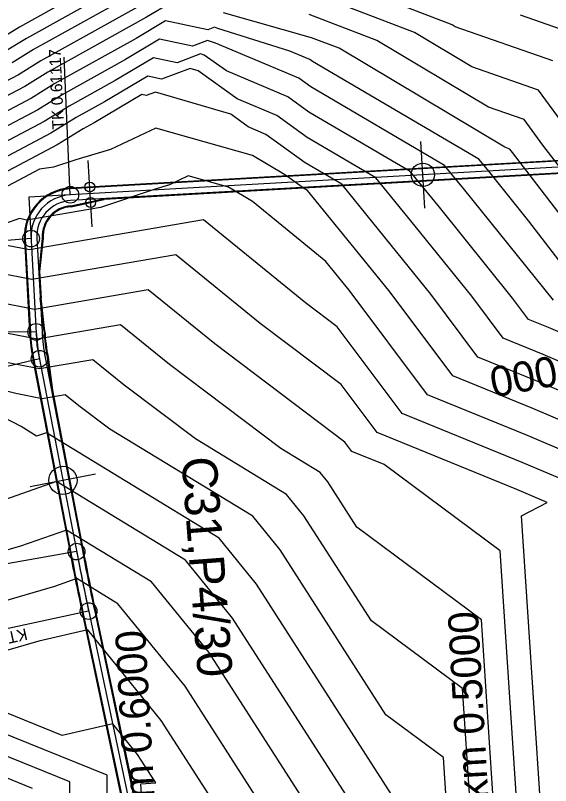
# Model space of a CAD drawing. Extents: x -549394 to -546608, y -1037055 to -1033629.
# Drawn here: x -547213.9 to -547053.3, y -1036262.8 to -1036031.6 of the extents above; entities that cross this region are included whole.
import ezdxf

# ---------------------------------------------------------------- set-up
doc = ezdxf.new("R2010")
doc.units = 0
for name, color, linetype in [('hlavni_vrst', 7, 'Continuous'), ('norm_vrst', 7, 'Continuous'), ('POLYGONY_SITUACE_PO', 7, 'Continuous'), ('u_sirka_7m', 7, 'Continuous'), ('x_navrh_C31', 7, 'Continuous'), ('x_osa_C31', 7, 'Continuous'), ('x_popis_oblouky_C31', 7, 'Continuous'), ('x_popis_pricne_rezy_C31', 7, 'Continuous'), ('x_popis_vely_C31', 7, 'Continuous')]:
    doc.layers.add(name, color=color, linetype=linetype)

msp = doc.modelspace()

# ---------------------------------------------------------------- linework, layer by layer
at = {"layer": 'hlavni_vrst'}
for p, q in [((-547161.94, -1036006.74), (-547212.7, -1036035.07)), ((-547048.3, -1036036.36), (-547062.3, -1036031.47)), ((-547168.82, -1036033.21), (-547177.7, -1036038.46)), ((-547156.15, -1036035.89), (-547168.82, -1036033.21)), ((-547212.7, -1036035.07), (-547218.78, -1036038.81)), ((-547154.16, -1036035.14), (-547156.15, -1036035.89)), ((-547153.11, -1036035.46), (-547154.16, -1036035.14)), ((-547131.51, -1036042.32), (-547153.11, -1036035.46)), ((-547177.7, -1036038.46), (-547202.05, -1036052.05)), ((-547125.59, -1036044.82), (-547131.51, -1036042.32)), ((-547124.74, -1036045.44), (-547125.59, -1036044.82)), ((-547074.84, -1036074.7), (-547124.74, -1036045.44)), ((-547202.05, -1036052.05), (-547209.1, -1036056.41)), ((-547209.1, -1036056.41), (-547236.25, -1036070.69)), ((-547171.78, -1036065.48), (-547185.32, -1036071.84)), ((-547142.72, -1036073.65), (-547171.78, -1036065.48)), ((-547185.32, -1036071.84), (-547195.72, -1036074.9)), ((-547132.86, -1036079.54), (-547142.72, -1036073.65)), ((-547195.72, -1036074.9), (-547202.48, -1036077.18)), ((-547072.26, -1036077.87), (-547074.84, -1036074.7)), ((-547206.64, -1036077.79), (-547230.36, -1036090.28)), ((-547202.48, -1036077.18), (-547206.64, -1036077.79)), ((-547059.82, -1036093.31), (-547072.26, -1036077.87)), ((-547127.44, -1036083.49), (-547132.86, -1036079.54)), ((-547126.27, -1036084.17), (-547127.44, -1036083.49)), ((-547108.3, -1036106.18), (-547126.27, -1036084.17)), ((-547046.99, -1036110.07), (-547059.82, -1036093.31)), ((-547101.47, -1036114.66), (-547108.3, -1036106.18)), ((-547082.66, -1036139.83), (-547101.47, -1036114.66)), ((-547207.41, -1036128.8), (-547228.09, -1036124.77)), ((-547182.34, -1036124.49), (-547207.41, -1036128.8)), ((-547167.65, -1036136.42), (-547182.34, -1036124.49)), ((-547134.25, -1036161.63), (-547167.65, -1036136.42)), ((-547058.66, -1036149.61), (-547082.66, -1036139.83)), ((-547033.64, -1036160.27), (-547058.66, -1036149.61)), ((-547122.45, -1036168.83), (-547134.25, -1036161.63)), ((-547120.18, -1036171.62), (-547122.45, -1036168.83)), ((-547111.44, -1036185.24), (-547120.18, -1036171.62)), ((-547198.53, -1036186.1), (-547212.4, -1036190.97)), ((-547173.02, -1036201.66), (-547198.53, -1036186.1)), ((-547074.04, -1036213.03), (-547111.44, -1036185.24)), ((-547212.4, -1036190.97), (-547223.21, -1036194.11)), ((-547155.85, -1036222.78), (-547173.02, -1036201.66)), ((-547069.17, -1036287.31), (-547074.04, -1036213.03)), ((-547118.07, -1036281.61), (-547155.85, -1036222.78)), ((-547197.57, -1036261.66), (-547233.92, -1036247.04)), ((-547197.5, -1036286.3), (-547197.57, -1036261.66))]:
    msp.add_line(p, q, dxfattribs=at)
at = {"layer": 'norm_vrst'}
for p, q in [((-547165.09, -1036013.08), (-547210.57, -1036038.46)), ((-547082.87, -1036034.38), (-547127.13, -1036017.3)), ((-547168.24, -1036019.43), (-547208.44, -1036041.86)), ((-547094.17, -1036036.74), (-547126.44, -1036024.29)), ((-547171.39, -1036025.77), (-547206.31, -1036045.26)), ((-547167.03, -1036027.67), (-547174.54, -1036032.12)), ((-547174.54, -1036032.12), (-547204.18, -1036048.65)), ((-547125.05, -1036038.26), (-547151.43, -1036030.85)), ((-547105.47, -1036039.1), (-547125.74, -1036031.27)), ((-547081.89, -1036034.96), (-547082.87, -1036034.38)), ((-547076.93, -1036047.04), (-547094.17, -1036036.74)), ((-547052.6, -1036045.2), (-547081.89, -1036034.96)), ((-547210.57, -1036038.46), (-547216.84, -1036042.33)), ((-547170.62, -1036038.75), (-547180.85, -1036044.81)), ((-547160.77, -1036040.83), (-547170.62, -1036038.75)), ((-547156.25, -1036039.14), (-547160.77, -1036040.83)), ((-547153.89, -1036039.87), (-547156.25, -1036039.14)), ((-547116.77, -1036041.45), (-547125.05, -1036038.26)), ((-547071.96, -1036059.11), (-547105.47, -1036039.1)), ((-547153.89, -1036039.87), (-547153.89, -1036039.87)), ((-547128.86, -1036050.44), (-547153.89, -1036039.87)), ((-547153.89, -1036039.87), (-547153.89, -1036039.87)), ((-547066.99, -1036071.18), (-547116.77, -1036041.45)), ((-547208.44, -1036041.86), (-547214.91, -1036045.85)), ((-547158.35, -1036043.14), (-547165.4, -1036045.77)), ((-547157.24, -1036043.48), (-547158.35, -1036043.14)), ((-547150.6, -1036048.26), (-547157.24, -1036043.48)), ((-547206.31, -1036045.26), (-547212.97, -1036049.37)), ((-547180.85, -1036044.81), (-547199.92, -1036055.45)), ((-547172.41, -1036044.29), (-547184, -1036051.15)), ((-547165.4, -1036045.77), (-547172.41, -1036044.29)), ((-547161.44, -1036047.51), (-547170.02, -1036050.71)), ((-547159.02, -1036048.23), (-547161.44, -1036047.51)), ((-547147.31, -1036056.65), (-547159.02, -1036048.23)), ((-547132.14, -1036056.06), (-547150.6, -1036048.26)), ((-547056.91, -1036054.03), (-547076.93, -1036047.04)), ((-547212.97, -1036049.37), (-547238.6, -1036062.86)), ((-547204.18, -1036048.65), (-547211.04, -1036052.89)), ((-547174.2, -1036049.83), (-547187.15, -1036057.5)), ((-547170.02, -1036050.71), (-547174.2, -1036049.83)), ((-547125.28, -1036053.05), (-547128.86, -1036050.44)), ((-547211.04, -1036052.89), (-547237.42, -1036066.77)), ((-547184, -1036051.15), (-547197.78, -1036058.84)), ((-547085.12, -1036076.6), (-547125.28, -1036053.05)), ((-547199.92, -1036055.45), (-547207.17, -1036059.92)), ((-547176, -1036055.37), (-547190.3, -1036063.84)), ((-547174.64, -1036055.66), (-547176, -1036055.37)), ((-547171.86, -1036054.62), (-547174.64, -1036055.66)), ((-547149.26, -1036061.27), (-547171.86, -1036054.62)), ((-547046.49, -1036068.33), (-547056.91, -1036054.03)), ((-547187.15, -1036057.5), (-547195.65, -1036062.24)), ((-547135.42, -1036061.67), (-547147.31, -1036056.65)), ((-547125.82, -1036060.66), (-547132.14, -1036056.06)), ((-547207.17, -1036059.92), (-547235.07, -1036074.61)), ((-547197.78, -1036058.84), (-547205.23, -1036063.44)), ((-547061.21, -1036062.86), (-547071.96, -1036059.11)), ((-547195.65, -1036062.24), (-547203.3, -1036066.96)), ((-547144.02, -1036065.04), (-547149.26, -1036061.27)), ((-547126.36, -1036068.27), (-547135.42, -1036061.67)), ((-547095.41, -1036078.49), (-547125.82, -1036060.66)), ((-547205.23, -1036063.44), (-547233.89, -1036078.53)), ((-547190.3, -1036063.84), (-547193.52, -1036065.64)), ((-547055.61, -1036070.55), (-547061.21, -1036062.86)), ((-547203.3, -1036066.96), (-547232.71, -1036082.44)), ((-547193.52, -1036065.64), (-547201.37, -1036070.48)), ((-547138.7, -1036067.29), (-547144.02, -1036065.04)), ((-547126.9, -1036075.88), (-547138.7, -1036067.29)), ((-547105.7, -1036080.38), (-547126.36, -1036068.27)), ((-547201.37, -1036070.48), (-547231.54, -1036086.36)), ((-547065.51, -1036071.7), (-547066.99, -1036071.18)), ((-547036.25, -1036095.83), (-547055.61, -1036070.55)), ((-547064.74, -1036072.76), (-547065.51, -1036071.7)), ((-547041.62, -1036102.95), (-547064.74, -1036072.76)), ((-547115.98, -1036082.28), (-547126.9, -1036075.88)), ((-547086.67, -1036089.19), (-547095.41, -1036078.49)), ((-547079.46, -1036083.53), (-547085.12, -1036076.6)), ((-547162.01, -1036079.79), (-547167.64, -1036082.44)), ((-547149.95, -1036083.19), (-547162.01, -1036079.79)), ((-547093.88, -1036094.86), (-547105.7, -1036080.38)), ((-547167.64, -1036082.44), (-547171.95, -1036083.71)), ((-547142.76, -1036087.48), (-547149.95, -1036083.19)), ((-547101.09, -1036100.52), (-547115.98, -1036082.28)), ((-547171.95, -1036083.71), (-547188.34, -1036089.23)), ((-547052.42, -1036117.11), (-547079.46, -1036083.53)), ((-547120.72, -1036105.46), (-547142.76, -1036087.48)), ((-547188.34, -1036089.23), (-547210.45, -1036093.02)), ((-547064.69, -1036116.5), (-547086.67, -1036089.19)), ((-547212.67, -1036092.59), (-547217.14, -1036094.19)), ((-547210.45, -1036093.02), (-547212.67, -1036092.59)), ((-547157.48, -1036093), (-547209.69, -1036101.97)), ((-547126.87, -1036117.85), (-547157.48, -1036093)), ((-547076.95, -1036115.89), (-547093.88, -1036094.86)), ((-547209.69, -1036101.97), (-547216.52, -1036100.64)), ((-547089.21, -1036115.27), (-547101.09, -1036100.52)), ((-547165.77, -1036103.5), (-547208.93, -1036110.91)), ((-547140.46, -1036124.04), (-547165.77, -1036103.5)), ((-547115.51, -1036111.85), (-547120.72, -1036105.46)), ((-547208.93, -1036110.91), (-547220.38, -1036108.68)), ((-547113.74, -1036114.04), (-547115.51, -1036111.85)), ((-547174.06, -1036114), (-547208.17, -1036119.85)), ((-547154.05, -1036130.23), (-547174.06, -1036114)), ((-547090.23, -1036145.49), (-547113.74, -1036114.04)), ((-547075.09, -1036134.17), (-547089.21, -1036115.27)), ((-547208.17, -1036119.85), (-547224.23, -1036116.72)), ((-547117.29, -1036125.08), (-547126.87, -1036117.85)), ((-547067.52, -1036128.5), (-547076.95, -1036115.89)), ((-547059.95, -1036122.84), (-547064.69, -1036116.5)), ((-547116.16, -1036142.38), (-547140.46, -1036124.04)), ((-547053.9, -1036125.3), (-547059.95, -1036122.84)), ((-547097.8, -1036151.15), (-547117.29, -1036125.08)), ((-547047.6, -1036127.99), (-547053.9, -1036125.3)), ((-547055.49, -1036133.41), (-547067.52, -1036128.5)), ((-547115.03, -1036159.69), (-547154.05, -1036130.23)), ((-547042.95, -1036138.75), (-547055.49, -1036133.41)), ((-547206.65, -1036137.74), (-547224.8, -1036134.2)), ((-547190.63, -1036134.99), (-547206.65, -1036137.74)), ((-547181.24, -1036142.61), (-547190.63, -1036134.99)), ((-547057.08, -1036141.51), (-547075.09, -1036134.17)), ((-547213.78, -1036145.14), (-547230.31, -1036140.87)), ((-547159.9, -1036158.72), (-547181.24, -1036142.61)), ((-547105.37, -1036156.82), (-547116.16, -1036142.38)), ((-547038.29, -1036149.51), (-547057.08, -1036141.51)), ((-547205.89, -1036146.68), (-547213.78, -1036145.14)), ((-547198.92, -1036145.49), (-547205.89, -1036146.68)), ((-547194.83, -1036148.8), (-547198.92, -1036145.49)), ((-547060.25, -1036157.72), (-547090.23, -1036145.49)), ((-547185.55, -1036155.81), (-547194.83, -1036148.8)), ((-547212.13, -1036155.02), (-547217.37, -1036152.31)), ((-547061.84, -1036165.82), (-547097.8, -1036151.15)), ((-547207.53, -1036157.95), (-547212.13, -1036155.02)), ((-547204.6, -1036156.93), (-547207.53, -1036157.95)), ((-547152.79, -1036188.53), (-547204.6, -1036156.93)), ((-547142.68, -1036181.96), (-547185.55, -1036155.81)), ((-547063.42, -1036173.92), (-547105.37, -1036156.82)), ((-547132.56, -1036175.4), (-547159.9, -1036158.72)), ((-547028.99, -1036171.02), (-547060.25, -1036157.72)), ((-547112.94, -1036162.48), (-547115.03, -1036159.69)), ((-547103.2, -1036166.45), (-547112.94, -1036162.48)), ((-547068.37, -1036192.34), (-547103.2, -1036166.45)), ((-547024.33, -1036181.78), (-547061.84, -1036165.82)), ((-547201.57, -1036171.51), (-547217.22, -1036177.01)), ((-547162.9, -1036195.1), (-547201.57, -1036171.51)), ((-547127.32, -1036181.85), (-547132.56, -1036175.4)), ((-547054.32, -1036177.8), (-547063.42, -1036173.92)), ((-547062.02, -1036181.85), (-547054.32, -1036177.8)), ((-547134.45, -1036192.08), (-547142.68, -1036181.96)), ((-547107.06, -1036213.39), (-547127.32, -1036181.85)), ((-547055.19, -1036285.88), (-547062.02, -1036181.85)), ((-547141.58, -1036202.31), (-547152.79, -1036188.53)), ((-547102.69, -1036241.55), (-547134.45, -1036192.08)), ((-547062.18, -1036286.6), (-547068.37, -1036192.34)), ((-547148.72, -1036212.54), (-547162.9, -1036195.1)), ((-547195.49, -1036200.69), (-547202.22, -1036203.05)), ((-547183.13, -1036208.23), (-547195.49, -1036200.69)), ((-547202.22, -1036203.05), (-547227.82, -1036210.48)), ((-547098.31, -1036269.7), (-547141.58, -1036202.31)), ((-547162.98, -1036233.01), (-547183.13, -1036208.23)), ((-547100.17, -1036288.14), (-547148.72, -1036212.54)), ((-547079.72, -1036233.71), (-547107.06, -1036213.39)), ((-547192.19, -1036216.09), (-547206.86, -1036219.43)), ((-547170.12, -1036243.24), (-547192.19, -1036216.09)), ((-547206.86, -1036219.43), (-547232.43, -1036226.86)), ((-547135.97, -1036275.08), (-547162.98, -1036233.01)), ((-547199.85, -1036247.75), (-547233.24, -1036234.32)), ((-547076.15, -1036288.03), (-547079.72, -1036233.71)), ((-547186.37, -1036259.67), (-547233.58, -1036240.68)), ((-547085.4, -1036254.39), (-547102.69, -1036241.55)), ((-547184.71, -1036244.3), (-547199.85, -1036247.75)), ((-547177.25, -1036253.47), (-547184.71, -1036244.3)), ((-547153.86, -1036268.55), (-547170.12, -1036243.24)), ((-547208.76, -1036263.66), (-547234.26, -1036253.4)), ((-547171.76, -1036262.02), (-547177.25, -1036253.47)), ((-547083.14, -1036288.74), (-547085.4, -1036254.39)), ((-547186.29, -1036291.65), (-547186.37, -1036259.67)), ((-547176.23, -1036262.27), (-547171.76, -1036262.02)), ((-547175.12, -1036282.28), (-547176.23, -1036262.27))]:
    msp.add_line(p, q, dxfattribs=at)
at = {"layer": 'POLYGONY_SITUACE_PO'}
for centre in [(-547197.42, -1036085.43), (-547209.19, -1036098.59), (-547207.66, -1036126.59), (-547206.67, -1036134.66), (-547195.53, -1036192.57), (-547191.93, -1036210.44)]:
    msp.add_circle(centre, 2.5, dxfattribs=at)
at = {"layer": 'u_sirka_7m'}
for centre, radius in [((-547091.63, -1036079.43), 3.5), ((-547191.59, -1036083.1), 1.5), ((-547191.32, -1036087.75), 1.5), ((-547199.64, -1036171.19), 4.23)]:
    msp.add_circle(centre, radius, dxfattribs=at)
at = {"layer": 'x_navrh_C31'}
for p, q in [((-547016.63, -1036073.41), (-547197.52, -1036083.69)), ((-547016.43, -1036076.91), (-547197.32, -1036087.18)), ((-547197.23, -1036088.79), (-547187.33, -1036086.61)), ((-547197.19, -1036089.04), (-547187.3, -1036086.86)), ((-547210.94, -1036098.69), (-547209.41, -1036126.69)), ((-547207.44, -1036098.5), (-547205.91, -1036126.5)), ((-547205.84, -1036098.41), (-547206.9, -1036108.48)), ((-547205.58, -1036098.42), (-547206.65, -1036108.49)), ((-547205.32, -1036126.47), (-547206.46, -1036116.51)), ((-547205.07, -1036126.45), (-547206.21, -1036116.49)), ((-547208.39, -1036134.99), (-547197.25, -1036192.9)), ((-547204.95, -1036134.33), (-547193.81, -1036192.24)), ((-547204.36, -1036134.21), (-547203.06, -1036144.15)), ((-547204.12, -1036134.17), (-547202.82, -1036144.11)), ((-547190.21, -1036210.08), (-547172.27, -1036294.98)), ((-547193.64, -1036210.8), (-547175.7, -1036295.7))]:
    msp.add_line(p, q, dxfattribs=at)
for points in [[(-547039.93, -1036074.49), (-547197.53, -1036083.44)], [(-547016.42, -1036077.16), (-547187.3, -1036086.86)], [(-547211.19, -1036098.7), (-547209.66, -1036126.7)], [(-547206.65, -1036108.49), (-547206.21, -1036116.49)], [(-547208.63, -1036135.04), (-547197.5, -1036192.95)], [(-547202.82, -1036144.11), (-547193.57, -1036192.19)], [(-547189.97, -1036210.03), (-547174.1, -1036285.13)], [(-547193.88, -1036210.85), (-547175.94, -1036295.75)]]:
    msp.add_lwpolyline(points, dxfattribs=at)
for centre, radius, start, end in [((-547196.71, -1036097.91), 14.5, 93.2502, 183.1242), ((-547196.71, -1036097.91), 14.25, 93.2502, 183.1242), ((-547196.71, -1036097.91), 10.75, 93.2502, 183.1242), ((-547196.71, -1036097.91), 9.14, 93.2502, 183.1242), ((-547196.71, -1036097.91), 8.89, 93.1222, 183.2522), ((-547147.75, -1036123.32), 62, 183.1242, 190.8879), ((-547147.75, -1036123.32), 61.75, 183.1242, 190.8879), ((-547147.75, -1036123.32), 58.25, 183.1242, 190.8879), ((-547147.75, -1036123.32), 57.65, 183.1242, 190.8879), ((-547147.75, -1036123.32), 57.4, 183.1168, 190.8954), ((-546213.53, -1036003.68), 1002, 190.88793, 191.93255), ((-546213.53, -1036003.68), 1001.75, 190.88793, 191.93255), ((-546213.53, -1036003.68), 998.25, 190.88793, 191.93255), ((-546213.53, -1036003.68), 998, 190.88793, 191.93255)]:
    msp.add_arc(centre, radius, start, end, dxfattribs=at)
at = {"layer": 'x_osa_C31'}
msp.add_lwpolyline([(-547007, -1036074.62), (-547209.87, -1036086.14), (-547207.44, -1036130.66), (-547193.81, -1036201.52), (-547173.1, -1036299.52), (-547166.67, -1036306.7), (-547163.9, -1036335.81), (-547195.59, -1036499.26)], dxfattribs=at)
for centre, radius, start, end in [((-547196.71, -1036097.91), 12.5, 93.2502, 183.1242), ((-547147.75, -1036123.32), 60, 183.1242, 190.8879), ((-546213.53, -1036003.68), 1000, 190.88793, 191.93255)]:
    msp.add_arc(centre, radius, start, end, dxfattribs=at)
at = {"layer": 'x_popis_oblouky_C31'}
for points in [[(-547197.42, -1036085.43), (-547199.25, -1036044.1)], [(-547209.19, -1036098.59), (-547250.42, -1036101.99)], [(-547207.66, -1036126.59), (-547249.03, -1036126.77)], [(-547206.67, -1036134.66), (-547246.92, -1036144.24)], [(-547195.53, -1036192.57), (-547236.28, -1036199.71)], [(-547191.93, -1036210.44), (-547232.36, -1036219.21)]]:
    msp.add_lwpolyline(points, dxfattribs=at)
at = {"layer": 'x_popis_pricne_rezy_C31'}
for points in [[(-547091.07, -1036089.41), (-547091.63, -1036079.43), (-547092.2, -1036069.44)], [(-547190.91, -1036095.08), (-547191.47, -1036085.1), (-547192.04, -1036075.11)], [(-547189.82, -1036169.3), (-547199.64, -1036171.19), (-547209.46, -1036173.08)]]:
    msp.add_lwpolyline(points, dxfattribs=at)

# ---------------------------------------------------------------- texts
at = {"layer": 'x_popis_oblouky_C31'}
for s, rotation, p in [('TK 0.61117', 92.5341, (-547199.29, -1036065.73)), ('KT 0.74415', 192.2433, (-547210.76, -1036215.55))]:
    msp.add_text(s, height=3.5, rotation=rotation, dxfattribs=at).set_placement(p)
at = {"layer": 'x_popis_pricne_rezy_C31'}
for s, rotation, p in [('PŘ 8 km 0.7000', 190.8879, (-546986.85, -1036121.03)), ('PŘ 6 km 0.5000', 93.2502, (-547070.2, -1036297)), ('PŘ 7 km 0.6000', 93.2502, (-547170.04, -1036302.67))]:
    msp.add_text(s, height=9.0627, rotation=rotation, dxfattribs=at).set_placement(p)
at = {"layer": 'x_popis_vely_C31'}
msp.add_text('C31,P4/30', height=10.5, rotation=274.2867, dxfattribs=at).set_placement((-547164.07, -1036164.42))

doc.saveas('drawing.dxf')
